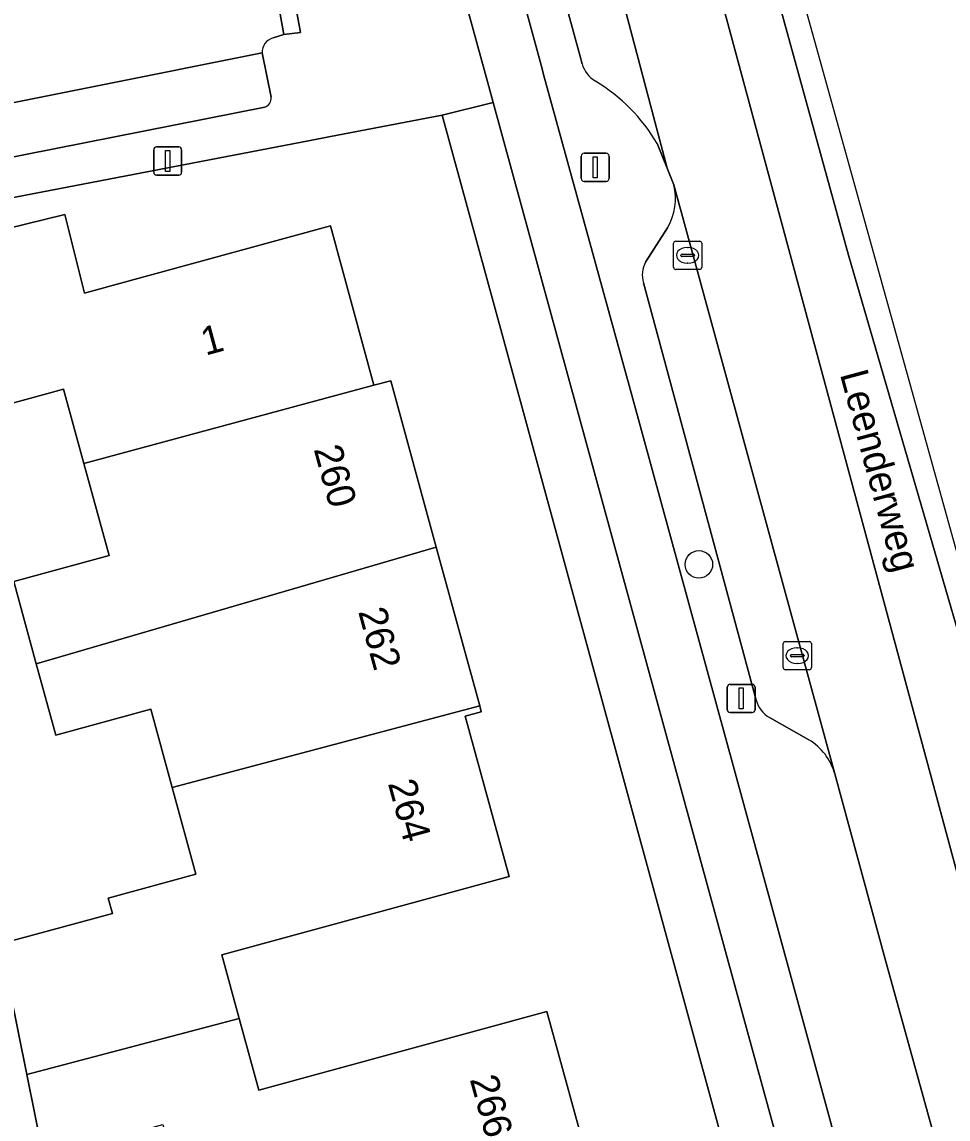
# Model space of a CAD drawing. Extents: x 162250 to 162661, y 380743 to 381606.
# Drawn here: x 162533.12 to 162566, y 381107.54 to 381146.51 of the extents above; entities that cross this region are included whole.
import ezdxf

# ---------------------------------------------------------------- set-up
doc = ezdxf.new("R2010")
doc.units = 0
for name, color, linetype in [('IMGEO_Berm_open', 7, 'Continuous'), ('IMGEO_Boom', 7, 'Continuous'), ('IMGEO_Erf', 7, 'Continuous'), ('IMGEO_Fietspad_gesloten', 7, 'Continuous'), ('IMGEO_Kolk', 7, 'Continuous'), ('IMGEO_Lichtmast', 7, 'Continuous'), ('IMGEO_Openbare_ruimte_label', 7, 'Continuous'), ('IMGEO_Pand', 7, 'Continuous'), ('IMGEO_Pand_nummerreeks', 7, 'Continuous'), ('IMGEO_Parkeervlak_open', 7, 'Continuous'), ('IMGEO_Rijbaan_regionaal_gesloten', 7, 'Continuous'), ('IMGEO_Voetpad_open', 7, 'Continuous'), ('IMGEO_Woonerf_open', 7, 'Continuous')]:
    doc.layers.add(name, color=color, linetype=linetype)

msp = doc.modelspace()

# ---------------------------------------------------------------- linework, layer by layer
at = {"layer": 'IMGEO_Berm_open'}
for points in [[(162553.008, 381145.025), (162552.925, 381145.33), (162550.374, 381154.672), (162550.34, 381154.796), (162542.98, 381181.61), (162542.491, 381181.463), (162541.461, 381185.086), (162541.982, 381185.24), (162537.767, 381200.743), (162536.398, 381200.372), (162539.144, 381190.342), (162540.943, 381183.77), (162548.984, 381154.395), (162551.592, 381144.84), (162551.645, 381144.647), (162554.806, 381133.124), (162560.736, 381111.446), (162562.992, 381103.198), (162573.052, 381066.398), (162577.335, 381050.801)], [(162556.267, 381140.725), (162556.025, 381141.32), (162555.673, 381142.187)], [(162555.263, 381137.978), (162556.045, 381139.198)], [(162559.191, 381122.421), (162555.188, 381137.246)], [(162561.057, 381121.014), (162559.661, 381121.801)], [(162565.639, 381106.468), (162563.768, 381113.225), (162561.982, 381119.806)]]:
    msp.add_lwpolyline(points, dxfattribs=at)
for centre, radius, start, end in [((162554.076, 381145.344), 1.115, 196.6042, 237.721), ((162550.293, 381139.052), 6.227, 30.2269, 59.2009), ((162554.276, 381140.235), 2.05, 329.6254, 13.8308), ((162556.075, 381137.525), 0.929, 150.8304, 197.4694), ((162560.2, 381122.698), 1.046, 195.3393, 238.9896), ((162559.995, 381119.243), 2.065, 15.8299, 59.0547)]:
    msp.add_arc(centre, radius, start, end, dxfattribs=at)
at = {"layer": 'IMGEO_Boom'}
msp.add_circle((162557.155, 381127.244), 0.489, dxfattribs=at)
at = {"layer": 'IMGEO_Erf'}
for points in [[(162590.707, 380987.36), (162583.561, 381013.383), (162568.771, 381067.243), (162550.23, 381135.191), (162548.044, 381143.201), (162544.023, 381142.428), (162543.35, 381142.299), (162530.217, 381139.774), (162529.938, 381139.71), (162526.734, 381139.031), (162526.506, 381138.986), (162505.307, 381134.801)], [(162530.49, 381138.654), (162534.642, 381139.666), (162535.347, 381136.88), (162536.248, 381137.126), (162544.072, 381139.266), (162545.62, 381133.605), (162546.214, 381133.765), (162547.83, 381127.859), (162549.374, 381122.215), (162549.431, 381122.005), (162548.86, 381121.849), (162550.416, 381116.161), (162540.22, 381113.372), (162540.837, 381111.114), (162541.533, 381108.569), (162551.761, 381111.366), (162553.33, 381105.631)], [(162533.63, 381123.706), (162532.83, 381126.631), (162536.219, 381127.558), (162535.325, 381130.827), (162534.602, 381133.471), (162531.174, 381132.533)], [(162503.939, 381132.922), (162506.878, 381118.071), (162530.585, 381122.589), (162530.755, 381121.745), (162532.362, 381113.762), (162536.335, 381114.848), (162536.185, 381115.393), (162539.296, 381116.244), (162538.456, 381119.316), (162537.695, 381122.096), (162534.322, 381121.173), (162533.63, 381123.706)]]:
    msp.add_lwpolyline(points, dxfattribs=at)
at = {"layer": 'IMGEO_Fietspad_gesloten'}
for points in [[(162508.721, 381294.058), (162520.721, 381250), (162524.95, 381234.475), (162526.439, 381228.987), (162532.158, 381208.274), (162537.019, 381190.487), (162538.98, 381183.33), (162547.107, 381153.663), (162547.143, 381153.533), (162549.695, 381144.216), (162549.852, 381143.643), (162552.836, 381132.744), (162558.72, 381111.249), (162561.27, 381101.934), (162571.085, 381066.091), (162575.392, 381050.363), (162582.804, 381023.355), (162585.413, 381013.87), (162586.64, 381009.407), (162588.336, 381003.241), (162600.985, 380956.955), (162611.456, 380918.623), (162619.54, 380889.111), (162626.231, 380864.638)], [(162611.747, 380924.889), (162608.338, 380937.386), (162606.977, 380942.372), (162603.154, 380956.316), (162590.219, 381003.716), (162588.433, 381010.254), (162587.309, 381014.367), (162584.526, 381024.553), (162577.335, 381050.801), (162573.052, 381066.398), (162562.992, 381103.198), (162560.736, 381111.446), (162554.806, 381133.124), (162551.645, 381144.647), (162551.592, 381144.84), (162548.984, 381154.395), (162540.943, 381183.77), (162539.144, 381190.342), (162536.398, 381200.372), (162535.609, 381203.223), (162535.353, 381204.147), (162534.863, 381206.056), (162528.007, 381231.163)]]:
    msp.add_lwpolyline(points, dxfattribs=at)
at = {"layer": 'IMGEO_Kolk'}
for p, q in [((162556.333, 381138.72), (162557.185, 381138.72)), ((162556.258, 381137.794), (162556.258, 381138.646)), ((162556.746, 381138.5), (162556.771, 381138.5)), ((162557.259, 381138.646), (162557.259, 381137.794)), ((162556.517, 381138.214), (162556.517, 381138.226)), ((162556.955, 381138.177), (162556.557, 381138.177)), ((162556.56, 381138.263), (162556.958, 381138.263)), ((162556.769, 381137.94), (162556.744, 381137.94)), ((162557.001, 381138.226), (162557.001, 381138.214)), ((162557.185, 381137.72), (162556.333, 381137.72)), ((162560.148, 381123.577), (162560.148, 381124.429)), ((162560.223, 381124.503), (162561.075, 381124.503)), ((162560.636, 381124.283), (162560.661, 381124.283)), ((162561.149, 381124.429), (162561.149, 381123.577)), ((162560.407, 381123.997), (162560.407, 381124.009)), ((162560.845, 381123.96), (162560.447, 381123.96)), ((162560.45, 381124.046), (162560.848, 381124.046)), ((162560.891, 381124.009), (162560.891, 381123.997)), ((162561.075, 381123.503), (162560.223, 381123.503)), ((162560.659, 381123.723), (162560.634, 381123.723))]:
    msp.add_line(p, q, dxfattribs=at)
for points in [[(162556.333, 381138.72), (162557.185, 381138.72)], [(162556.258, 381137.794), (162556.258, 381138.646)], [(162557.259, 381138.646), (162557.259, 381137.794)], [(162557.185, 381137.72), (162556.333, 381137.72)], [(162560.148, 381123.577), (162560.148, 381124.429)], [(162560.223, 381124.503), (162561.075, 381124.503)], [(162561.149, 381124.429), (162561.149, 381123.577)], [(162561.075, 381123.503), (162560.223, 381123.503)]]:
    msp.add_lwpolyline(points, dxfattribs=at)
for centre, radius, start, end in [((162556.335, 381138.644), 0.0765, 91.552, 178.448), ((162556.335, 381138.644), 0.0765, 91.552, 178.448), ((162557.183, 381138.644), 0.0765, 1.552, 88.448), ((162557.183, 381138.644), 0.0765, 1.552, 88.448), ((162556.557, 381138.223), 0.0403, 85.8775, 175.7526), ((162556.554, 381138.213), 0.0366, 178.938, 274.7102), ((162556.958, 381138.22), 0.043, 264.8664, 352.4533), ((162556.962, 381138.225), 0.0386, 1.7309, 96.639), ((162556.335, 381137.796), 0.0765, 181.552, 268.448), ((162556.335, 381137.796), 0.0765, 181.552, 268.448), ((162557.183, 381137.796), 0.0765, 271.552, 358.448), ((162557.183, 381137.796), 0.0765, 271.552, 358.448), ((162560.225, 381124.427), 0.0765, 91.552, 178.448), ((162560.225, 381124.427), 0.0765, 91.552, 178.448), ((162561.073, 381124.427), 0.0765, 1.552, 88.448), ((162561.073, 381124.427), 0.0765, 1.552, 88.448), ((162560.447, 381124.006), 0.0403, 85.8775, 175.7526), ((162560.444, 381123.996), 0.0366, 178.938, 274.7102), ((162560.848, 381124.003), 0.043, 264.8664, 352.4533), ((162560.852, 381124.008), 0.0386, 1.7309, 96.639), ((162560.225, 381123.579), 0.0765, 181.552, 268.448), ((162560.225, 381123.579), 0.0765, 181.552, 268.448), ((162561.073, 381123.579), 0.0765, 271.552, 358.448), ((162561.073, 381123.579), 0.0765, 271.552, 358.448)]:
    msp.add_arc(centre, radius, start, end, dxfattribs=at)
for centre, major_axis, ratio, start_param, end_param in [((162556.745, 381138.22), (-0.387, 0.002), 0.722429, 4.712389, 7.853982), ((162556.77, 381138.22), (-0.39, 0.002), 0.717154, 1.570796, 4.712389), ((162560.635, 381124.003), (-0.387, 0.002), 0.722429, 4.712389, 7.853982), ((162560.66, 381124.003), (-0.39, 0.002), 0.717154, 1.570796, 4.712389)]:
    msp.add_ellipse(centre, major_axis=major_axis, ratio=ratio, start_param=start_param, end_param=end_param, dxfattribs=at)
at = {"layer": 'IMGEO_Lichtmast'}
for p, q in [((162537.803, 381141.168), (162537.803, 381141.968)), ((162537.803, 381141.968), (162537.803, 381141.168)), ((162537.903, 381142.068), (162538.693, 381142.068)), ((162538.693, 381142.068), (162537.903, 381142.068)), ((162538.793, 381141.968), (162538.793, 381141.168)), ((162538.793, 381141.168), (162538.793, 381141.968)), ((162553.078, 381141.844), (162553.868, 381141.844)), ((162553.868, 381141.844), (162553.078, 381141.844)), ((162552.978, 381140.944), (162552.978, 381141.744)), ((162552.978, 381141.744), (162552.978, 381140.944)), ((162553.968, 381141.744), (162553.968, 381140.944)), ((162553.968, 381140.944), (162553.968, 381141.744)), ((162538.693, 381141.068), (162537.903, 381141.068)), ((162537.903, 381141.068), (162538.693, 381141.068)), ((162553.868, 381140.844), (162553.078, 381140.844)), ((162553.078, 381140.844), (162553.868, 381140.844)), ((162558.163, 381122.083), (162558.163, 381122.883)), ((162558.163, 381122.883), (162558.163, 381122.083)), ((162558.263, 381122.983), (162559.053, 381122.983)), ((162559.053, 381122.983), (162558.263, 381122.983)), ((162559.153, 381122.883), (162559.153, 381122.083)), ((162559.153, 381122.083), (162559.153, 381122.883)), ((162559.053, 381121.983), (162558.263, 381121.983)), ((162558.263, 381121.983), (162559.053, 381121.983))]:
    msp.add_line(p, q, dxfattribs=at)
for points in [[(162538.223, 381141.943), (162538.373, 381141.943), (162538.373, 381141.193), (162538.223, 381141.193), (162538.223, 381141.943)], [(162553.398, 381141.719), (162553.548, 381141.719), (162553.548, 381140.969), (162553.398, 381140.969), (162553.398, 381141.719)], [(162558.583, 381122.858), (162558.733, 381122.858), (162558.733, 381122.108), (162558.583, 381122.108), (162558.583, 381122.858)]]:
    msp.add_lwpolyline(points, dxfattribs=at)
for centre, start, end in [((162537.903, 381141.968), 90, 180), ((162537.903, 381141.968), 90, 180), ((162538.693, 381141.968), 0, 90), ((162538.693, 381141.968), 360, 90), ((162553.078, 381141.744), 90, 180), ((162553.078, 381141.744), 90, 180), ((162553.868, 381141.744), 0, 90), ((162553.868, 381141.744), 360, 90), ((162537.903, 381141.168), 180, 270), ((162537.903, 381141.168), 180, 270), ((162538.693, 381141.168), 270, 0), ((162538.693, 381141.168), 270, 0), ((162553.078, 381140.944), 180, 270), ((162553.078, 381140.944), 180, 270), ((162553.868, 381140.944), 270, 0), ((162553.868, 381140.944), 270, 0), ((162558.263, 381122.883), 90, 180), ((162558.263, 381122.883), 90, 180), ((162559.053, 381122.883), 0, 90), ((162559.053, 381122.883), 360, 90), ((162558.263, 381122.083), 180, 270), ((162558.263, 381122.083), 180, 270), ((162559.053, 381122.083), 270, 0), ((162559.053, 381122.083), 270, 0)]:
    msp.add_arc(centre, 0.1, start, end, dxfattribs=at)
at = {"layer": 'IMGEO_Pand'}
for points in [[(162528.246, 381130.613), (162531.429, 381131.239), (162531.174, 381132.533), (162534.602, 381133.471), (162535.325, 381130.827), (162545.62, 381133.605), (162544.072, 381139.266), (162536.248, 381137.126), (162535.347, 381136.88), (162534.642, 381139.666), (162530.49, 381138.654), (162530.258, 381138.598), (162530.993, 381135.689), (162530.58, 381135.576), (162530.368, 381136.65), (162527.076, 381136.002)], [(162547.83, 381127.859), (162546.214, 381133.765), (162545.62, 381133.605), (162535.325, 381130.827), (162536.219, 381127.558), (162532.83, 381126.631), (162533.63, 381123.706)], [(162547.83, 381127.859), (162533.63, 381123.706), (162534.322, 381121.173), (162537.695, 381122.096), (162538.456, 381119.316), (162549.374, 381122.215)], [(162549.374, 381122.215), (162538.456, 381119.316), (162539.296, 381116.244), (162536.185, 381115.393), (162536.335, 381114.848), (162532.362, 381113.762), (162533.293, 381109.132), (162540.837, 381111.114), (162540.22, 381113.372), (162550.416, 381116.161), (162548.86, 381121.849), (162549.431, 381122.005)], [(162542.936, 381102.845), (162553.915, 381105.543), (162553.852, 381105.774), (162553.33, 381105.631), (162551.761, 381111.366), (162541.533, 381108.569), (162540.837, 381111.114), (162533.293, 381109.132), (162533.885, 381106.188), (162536.488, 381106.9), (162538.126, 381107.348), (162538.858, 381104.675), (162542.186, 381105.585)]]:
    msp.add_lwpolyline(points, close=True, dxfattribs=at)
at = {"layer": 'IMGEO_Parkeervlak_open'}
for points in [[(162541.968, 381143.837), (162541.654, 381145.406), (162529.651, 381143.002), (162530.009, 381141.165), (162541.744, 381143.487)], [(162561.982, 381119.806), (162556.267, 381140.725)], [(162556.045, 381139.198), (162555.263, 381137.978)], [(162555.188, 381137.246), (162559.191, 381122.421)], [(162559.661, 381121.801), (162561.057, 381121.014)]]:
    msp.add_lwpolyline(points, dxfattribs=at)
for centre, radius, start, end in [((162541.644, 381143.798), 0.327, 287.8672, 6.8943), ((162554.276, 381140.235), 2.05, 329.6254, 13.8308), ((162556.075, 381137.525), 0.929, 150.8304, 197.4694), ((162560.2, 381122.698), 1.046, 195.3393, 238.9896), ((162559.995, 381119.243), 2.065, 15.8299, 59.0547)]:
    msp.add_arc(centre, radius, start, end, dxfattribs=at)
at = {"layer": 'IMGEO_Rijbaan_regionaal_gesloten'}
for points in [[(162604.23, 380992.009), (162599.016, 381010.476), (162591.435, 381037.32), (162559.589, 381151.874), (162545.39, 381202.947), (162544.673, 381202.753), (162544.818, 381202.219), (162545.081, 381201.258)], [(162543.432, 381200.793), (162543.152, 381201.827), (162543.029, 381202.295), (162540.124, 381201.475), (162556.025, 381141.32), (162556.267, 381140.725), (162561.982, 381119.806), (162563.768, 381113.225), (162565.639, 381106.468), (162577.173, 381064.266), (162584.449, 381036.623), (162587.606, 381025.501), (162590.528, 381015.212), (162591.173, 381012.938), (162595.042, 380999.313), (162597.541, 380990.23), (162600.546, 380991.029), (162599.675, 380994.301)], [(162540.124, 381201.475), (162537.767, 381200.743), (162541.982, 381185.24), (162542.98, 381181.61), (162550.34, 381154.796), (162550.374, 381154.672), (162552.925, 381145.33), (162553.008, 381145.025)], [(162555.673, 381142.187), (162556.025, 381141.32), (162540.124, 381201.475)], [(162569.845, 381112.873), (162562.469, 381138.221), (162546.555, 381196.038), (162545.104, 381200.933)], [(162545.104, 381200.933), (162546.555, 381196.038), (162562.469, 381138.221), (162569.845, 381112.873)], [(162543.648, 381200.38), (162544.792, 381196.117), (162567.409, 381112.237)], [(162567.409, 381112.237), (162544.792, 381196.117), (162543.648, 381200.38)]]:
    msp.add_lwpolyline(points, dxfattribs=at)
for centre, radius, start, end in [((162554.076, 381145.344), 1.115, 196.6042, 237.721), ((162550.293, 381139.052), 6.227, 30.2269, 59.2009)]:
    msp.add_arc(centre, radius, start, end, dxfattribs=at)
at = {"layer": 'IMGEO_Voetpad_open'}
for points in [[(162505.307, 381134.801), (162526.506, 381138.986), (162526.734, 381139.031), (162529.938, 381139.71), (162530.217, 381139.774), (162543.35, 381142.299), (162544.023, 381142.428), (162548.044, 381143.201), (162549.852, 381143.643), (162549.695, 381144.216), (162547.143, 381153.533)], [(162525.301, 381146.942), (162541.689, 381150.159), (162542.254, 381150.28), (162543.014, 381146.137), (162542.424, 381146.057), (162542.043, 381145.939)], [(162541.654, 381145.406), (162541.968, 381143.837)], [(162541.744, 381143.487), (162530.009, 381141.165), (162526.385, 381140.474), (162526.408, 381140.279), (162525.057, 381139.985), (162501.645, 381135.35)], [(162561.27, 381101.934), (162558.72, 381111.249), (162552.836, 381132.744), (162549.852, 381143.643), (162548.044, 381143.201), (162550.23, 381135.191), (162568.771, 381067.243), (162583.561, 381013.383), (162590.707, 380987.36)], [(162548.818, 381031.958), (162533.885, 381106.188), (162533.293, 381109.132), (162532.362, 381113.762), (162530.755, 381121.745), (162529.559, 381121.504), (162532.063, 381109.148), (162532.568, 381106.657), (162533.059, 381104.234), (162534.676, 381096.835), (162535.65, 381092.01), (162536.554, 381087.296), (162537.084, 381084.729), (162540.133, 381069.953), (162540.637, 381067.452), (162542.17, 381059.531)]]:
    msp.add_lwpolyline(points, dxfattribs=at)
for centre, radius, start, end in [((162542.168, 381145.439), 0.515, 104.0532, 183.7006), ((162541.644, 381143.798), 0.327, 287.8672, 6.8943)]:
    msp.add_arc(centre, radius, start, end, dxfattribs=at)
at = {"layer": 'IMGEO_Woonerf_open'}
for points in [[(162542.043, 381145.939), (162542.424, 381146.057), (162541.689, 381150.159), (162525.301, 381146.942)], [(162524.683, 381147.301), (162524.521, 381148.253), (162520.127, 381147.412), (162520.245, 381146.644), (162517.045, 381146.048), (162517.37, 381144.297), (162506.516, 381142.212), (162507.155, 381139.028), (162524.014, 381142.284), (162524.397, 381142.226), (162526.17, 381140.989), (162526.391, 381140.645), (162526.385, 381140.474), (162530.009, 381141.165), (162529.651, 381143.002), (162541.654, 381145.406)]]:
    msp.add_lwpolyline(points, dxfattribs=at)
msp.add_lwpolyline([(162542.254, 381150.28), (162541.689, 381150.159), (162542.424, 381146.057), (162543.014, 381146.137)], close=True, dxfattribs=at)
msp.add_arc((162542.168, 381145.439), 0.515, 104.0532, 183.7006, dxfattribs=at)

# ---------------------------------------------------------------- texts
at = {"layer": 'IMGEO_Openbare_ruimte_label'}
msp.add_text('Leenderweg', height=1, rotation=285.1345, dxfattribs=at).set_placement((162562.157, 381134.002))
at = {"layer": 'IMGEO_Pand_nummerreeks'}
for s, rotation, p in [('1', 15.2961, (162539.639, 381134.653)), ('260', 285.2992, (162543.477, 381131.338)), ('262', 285.2992, (162545.055, 381125.569)), ('264', 285.2978, (162546.11, 381119.469)), ('266', 285.3008, (162549.017, 381108.962))]:
    msp.add_text(s, height=1, rotation=rotation, dxfattribs=at).set_placement(p)

doc.saveas('drawing.dxf')
